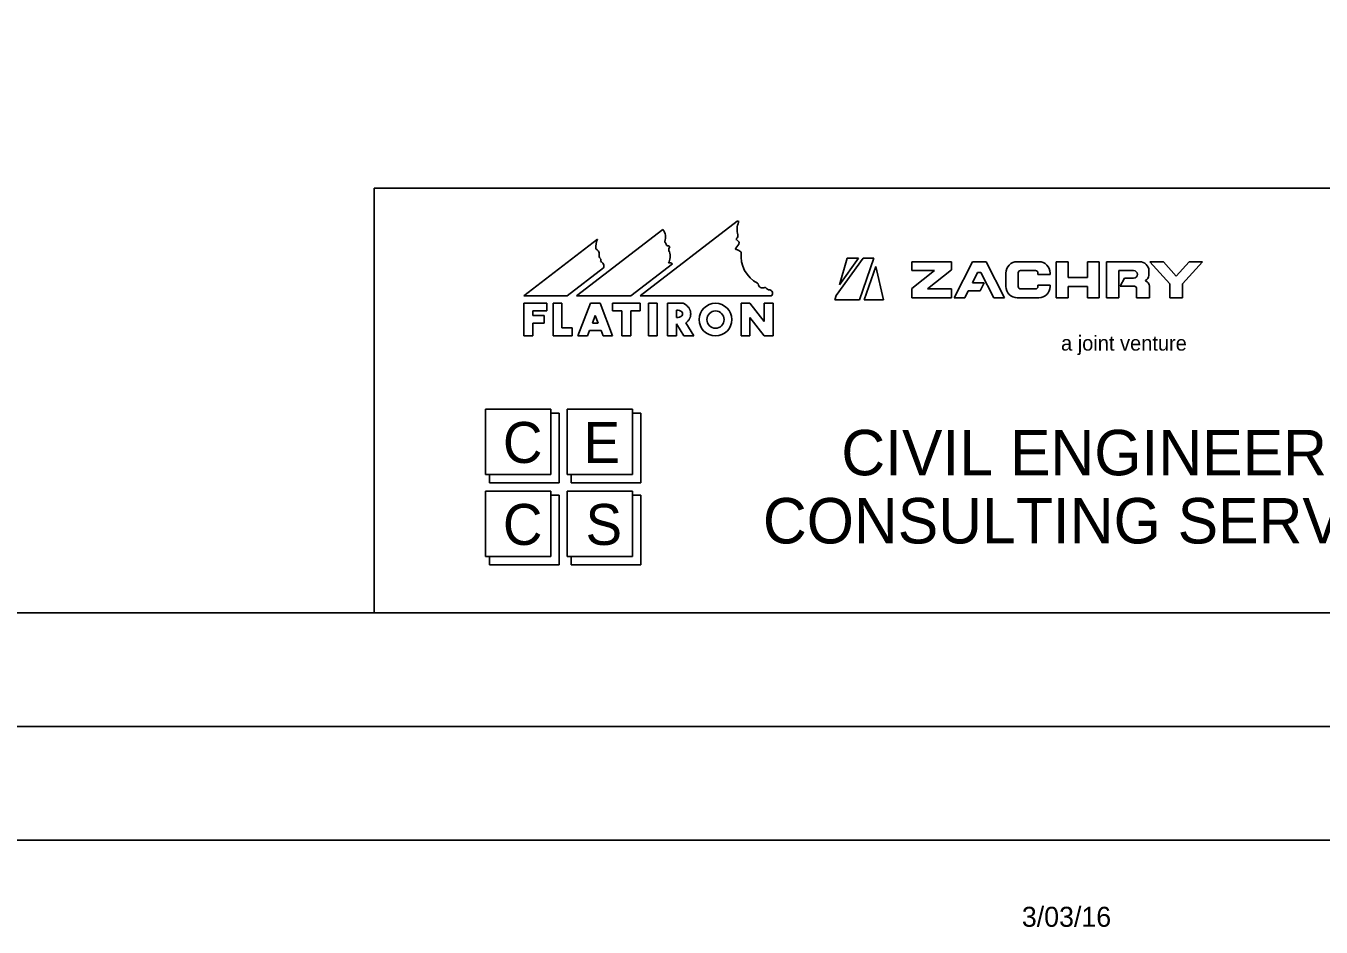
# Model space of a CAD drawing. Extents: x -2251 to 10196, y -13470 to 1199.
# Drawn here: x 6237 to 6522.4, y -1469.8 to -1271.4 of the extents above; entities that cross this region are included whole.
import ezdxf

# ---------------------------------------------------------------- set-up
doc = ezdxf.new("R2010")
doc.units = 0
for name, color, linetype in [('Level 3', 7, 'Continuous'), ('RD_SHT_Bndy', 7, 'Continuous'), ('RD_SHT_Iplotshp', 7, 'Continuous'), ('RD_SHT_Logo', 7, 'Continuous'), ('RD_SHT_Misc1', 7, 'Continuous'), ('RD_SHT_Snap', 7, 'Continuous'), ('RD_SHT_TX', 7, 'Continuous')]:
    doc.layers.add(name, color=color, linetype=linetype)

msp = doc.modelspace()

# ---------------------------------------------------------------- linework, layer by layer
at = {"layer": 'Level 3'}
msp.add_line((6465.07, -1363.99), (6465.07, -1363.99), dxfattribs=at)
msp.add_line((6465.07, -1363.99), (6465.07, -1363.99), dxfattribs=at)
msp.add_line((6465.07, -1363.99), (6465.07, -1363.99), dxfattribs=at)
msp.add_line((6465.07, -1363.99), (6465.07, -1363.99), dxfattribs=at)
at = {"layer": 'RD_SHT_Bndy'}
for p, q in [((5103.1, -1400.65), (6778.1, -1400.65)), ((6791.65, -1425.65), (5031.65, -1425.65)), ((6791.6, -1450.7), (5031.6, -1450.65))]:
    msp.add_line(p, q, dxfattribs=at)
at = {"layer": 'RD_SHT_Iplotshp'}
msp.add_lwpolyline([(4996.65, -325.65), (6796.65, -325.65), (6796.65, -1425.65), (4996.65, -1425.65)], close=True, dxfattribs=at)
at = {"layer": 'RD_SHT_Logo'}
for p, q in [((6372.32, -1330.86), (6393.74, -1314.44)), ((6346.7, -1330.86), (6362.98, -1318.38)), ((6377.35, -1316.27), (6358.31, -1330.86)), ((6370.3, -1330.86), (6379.48, -1323.82)), ((6415.56, -1330.77), (6421.47, -1322.59)), ((6420.48, -1322.59), (6416.24, -1328.47)), ((6416.24, -1328.47), (6417.96, -1322.59)), ((6417.96, -1322.59), (6420.48, -1322.59)), ((6423.82, -1322.59), (6420.68, -1331.76)), ((6421.47, -1322.59), (6423.82, -1322.59)), ((6440.93, -1323.35), (6432.22, -1323.35)), ((6432.22, -1323.35), (6432.22, -1325.3)), ((6440.93, -1325.16), (6440.93, -1323.35)), ((6445.58, -1323.35), (6441.53, -1331.3)), ((6448.58, -1323.35), (6445.58, -1323.35)), ((6452.63, -1331.3), (6448.58, -1323.35)), ((6455.44, -1323.35), (6460.18, -1323.35)), ((6466.62, -1323.35), (6464.02, -1323.35)), ((6464.02, -1323.35), (6464.02, -1331.3)), ((6466.62, -1326.8), (6466.62, -1323.35)), ((6470.9, -1323.35), (6470.9, -1326.8)), ((6473.51, -1323.35), (6470.9, -1323.35)), ((6473.5, -1331.3), (6473.51, -1323.35)), ((6482.43, -1323.35), (6475.13, -1323.35)), ((6475.13, -1323.35), (6475.13, -1331.3)), ((6484.68, -1323.35), (6487.64, -1323.35)), ((6489.08, -1328.24), (6484.68, -1323.35)), ((6487.64, -1323.35), (6490.48, -1326.51)), ((6490.48, -1326.51), (6493.32, -1323.35)), ((6496.28, -1323.35), (6491.88, -1328.24)), ((6493.32, -1323.35), (6496.28, -1323.35)), ((6364.27, -1324.74), (6356.29, -1330.86)), ((6424.24, -1324.44), (6421.74, -1331.76)), ((6425.99, -1331.76), (6424.24, -1324.44)), ((6437.2, -1325.3), (6432.22, -1329.24)), ((6432.22, -1325.3), (6437.2, -1325.3)), ((6435.63, -1329.35), (6440.93, -1325.16)), ((6445.57, -1327.99), (6446.71, -1325.75)), ((6446.71, -1325.75), (6447.44, -1325.75)), ((6447.44, -1325.75), (6450.27, -1331.3)), ((6452.94, -1328.8), (6452.94, -1325.85)), ((6455.64, -1325.8), (6455.64, -1328.85)), ((6459.48, -1325.3), (6456.14, -1325.3)), ((6459.98, -1326.15), (6459.98, -1325.8)), ((6462.68, -1326.15), (6459.98, -1326.15)), ((6462.68, -1325.85), (6462.68, -1326.15)), ((6470.9, -1326.8), (6466.62, -1326.8)), ((6477.83, -1331.3), (6477.83, -1325.31)), ((6477.83, -1325.31), (6481.07, -1325.31)), ((6479.03, -1326.97), (6478.11, -1328.77)), ((6481.07, -1326.97), (6479.03, -1326.97)), ((6484.43, -1326.36), (6484.43, -1325.35)), ((6432.22, -1329.24), (6432.22, -1331.3)), ((6440.93, -1329.35), (6435.63, -1329.35)), ((6440.93, -1331.3), (6440.93, -1329.35)), ((6443.88, -1331.3), (6444.65, -1329.79)), ((6444.65, -1329.79), (6447.23, -1329.79)), ((6448.15, -1327.99), (6445.57, -1327.99)), ((6447.23, -1329.79), (6448.15, -1327.99)), ((6456.14, -1329.35), (6459.48, -1329.35)), ((6459.98, -1328.5), (6462.68, -1328.5)), ((6459.98, -1328.85), (6459.98, -1328.5)), ((6462.68, -1328.5), (6462.68, -1328.8)), ((6466.62, -1331.3), (6466.62, -1328.8)), ((6466.62, -1328.8), (6470.9, -1328.8)), ((6470.9, -1328.8), (6470.9, -1331.3)), ((6478.11, -1328.77), (6481.24, -1328.77)), ((6481.74, -1329.27), (6481.74, -1331.3)), ((6483.68, -1327.6), (6483.68, -1327.47)), ((6484.54, -1331.3), (6484.54, -1328.76)), ((6489.08, -1331.3), (6489.08, -1328.24)), ((6491.88, -1328.24), (6491.88, -1331.3)), ((6356.29, -1330.86), (6346.7, -1330.86)), ((6346.72, -1339.7), (6346.72, -1332.5)), ((6346.72, -1332.5), (6351.82, -1332.5)), ((6351.82, -1332.5), (6351.82, -1334.15)), ((6355.12, -1332.5), (6353.17, -1332.5)), ((6353.17, -1332.5), (6353.17, -1339.7)), ((6355.12, -1337.9), (6355.12, -1332.5)), ((6358.31, -1330.86), (6370.3, -1330.86)), ((6361.42, -1332.5), (6358.65, -1339.71)), ((6363.52, -1332.5), (6361.42, -1332.5)), ((6366.28, -1339.71), (6363.52, -1332.5)), ((6366.22, -1334.15), (6366.22, -1332.5)), ((6366.22, -1332.5), (6372.37, -1332.5)), ((6401.19, -1330.86), (6372.32, -1330.86)), ((6372.37, -1332.5), (6372.37, -1334.15)), ((6374.17, -1339.71), (6374.17, -1332.5)), ((6374.17, -1332.5), (6376.12, -1332.5)), ((6376.12, -1332.5), (6376.12, -1339.71)), ((6381.8, -1332.5), (6378.38, -1332.5)), ((6378.38, -1332.5), (6378.38, -1339.71)), ((6396.52, -1332.5), (6394.57, -1332.5)), ((6394.57, -1332.5), (6394.57, -1339.71)), ((6399.67, -1336.53), (6396.52, -1332.5)), ((6401.62, -1332.5), (6399.67, -1332.5)), ((6399.67, -1332.5), (6399.67, -1336.53)), ((6401.62, -1339.71), (6401.62, -1332.5)), ((6415.27, -1331.76), (6415.56, -1330.77)), ((6420.68, -1331.76), (6415.27, -1331.76)), ((6421.74, -1331.76), (6425.99, -1331.76)), ((6432.22, -1331.3), (6440.93, -1331.3)), ((6441.53, -1331.3), (6443.88, -1331.3)), ((6450.27, -1331.3), (6452.63, -1331.3)), ((6460.18, -1331.3), (6455.44, -1331.3)), ((6464.02, -1331.3), (6466.62, -1331.3)), ((6470.9, -1331.3), (6473.5, -1331.3)), ((6475.13, -1331.3), (6477.83, -1331.3)), ((6481.74, -1331.3), (6484.54, -1331.3)), ((6491.88, -1331.3), (6489.08, -1331.3)), ((6351.82, -1334.15), (6348.67, -1334.15)), ((6348.67, -1334.15), (6348.67, -1335.21)), ((6348.67, -1335.21), (6351.22, -1335.21)), ((6351.22, -1335.21), (6351.22, -1336.86)), ((6361.83, -1336.86), (6362.47, -1335.2)), ((6362.47, -1335.2), (6363.1, -1336.86)), ((6368.32, -1334.15), (6366.22, -1334.15)), ((6368.32, -1339.71), (6368.32, -1334.15)), ((6372.37, -1334.15), (6370.27, -1334.15)), ((6370.27, -1334.15), (6370.27, -1339.71)), ((6380.33, -1335.66), (6380.33, -1334.01)), ((6351.22, -1336.86), (6348.67, -1336.86)), ((6348.67, -1336.86), (6348.67, -1339.7)), ((6357.37, -1337.9), (6355.12, -1337.9)), ((6357.37, -1339.71), (6357.37, -1337.9)), ((6363.1, -1336.86), (6361.83, -1336.86)), ((6380.33, -1339.71), (6380.33, -1337.02)), ((6380.33, -1337.02), (6381.94, -1339.71)), ((6384.16, -1339.71), (6382.43, -1336.82)), ((6396.52, -1339.71), (6396.52, -1335.67)), ((6396.52, -1335.67), (6399.67, -1339.71)), ((6348.67, -1339.7), (6346.72, -1339.7)), ((6353.17, -1339.7), (6357.37, -1339.71)), ((6358.65, -1339.71), (6360.74, -1339.71)), ((6360.74, -1339.71), (6361.2, -1338.51)), ((6361.2, -1338.51), (6363.74, -1338.51)), ((6363.74, -1338.51), (6364.2, -1339.71)), ((6364.2, -1339.71), (6366.28, -1339.71)), ((6370.27, -1339.71), (6368.32, -1339.71)), ((6376.12, -1339.71), (6374.17, -1339.71)), ((6378.38, -1339.71), (6380.33, -1339.71)), ((6381.94, -1339.71), (6384.16, -1339.71)), ((6394.57, -1339.71), (6396.52, -1339.71)), ((6399.67, -1339.71), (6401.62, -1339.71)), ((6352.67, -1355.79), (6338.28, -1355.79)), ((6338.28, -1355.79), (6338.28, -1370.23)), ((6352.67, -1370.23), (6352.67, -1355.79)), ((6352.67, -1355.79), (6352.67, -1370.23)), ((6354.48, -1356.7), (6352.67, -1356.7)), ((6354.48, -1372.03), (6354.48, -1356.7)), ((6370.67, -1355.79), (6356.27, -1355.79)), ((6356.27, -1355.79), (6356.27, -1370.23)), ((6370.67, -1370.23), (6370.67, -1355.79)), ((6370.67, -1355.79), (6370.67, -1370.23)), ((6372.48, -1356.7), (6370.67, -1356.7)), ((6372.48, -1372.03), (6372.48, -1356.7)), ((6338.28, -1370.23), (6352.67, -1370.23)), ((6352.67, -1370.23), (6339.17, -1370.23)), ((6339.17, -1370.23), (6339.17, -1372.03)), ((6339.17, -1372.03), (6354.48, -1372.03)), ((6356.27, -1370.23), (6370.67, -1370.23)), ((6370.67, -1370.23), (6357.18, -1370.23)), ((6357.18, -1370.23), (6357.18, -1372.03)), ((6357.18, -1372.03), (6372.48, -1372.03)), ((6352.67, -1373.84), (6338.28, -1373.84)), ((6338.28, -1373.84), (6338.28, -1388.27)), ((6352.67, -1388.27), (6352.67, -1373.84)), ((6352.67, -1373.84), (6352.67, -1388.27)), ((6354.48, -1374.74), (6352.67, -1374.74)), ((6354.48, -1390.07), (6354.48, -1374.74)), ((6370.67, -1373.84), (6356.27, -1373.84)), ((6356.27, -1373.84), (6356.27, -1388.27)), ((6370.67, -1388.27), (6370.67, -1373.84)), ((6370.67, -1373.84), (6370.67, -1388.27)), ((6372.48, -1374.74), (6370.67, -1374.74)), ((6372.48, -1390.07), (6372.48, -1374.74)), ((6338.28, -1388.27), (6352.67, -1388.27)), ((6352.67, -1388.27), (6339.17, -1388.27)), ((6339.17, -1388.27), (6339.17, -1390.07)), ((6356.27, -1388.27), (6370.67, -1388.27)), ((6370.67, -1388.27), (6357.18, -1388.27)), ((6357.18, -1388.27), (6357.18, -1390.07)), ((6339.17, -1390.07), (6354.48, -1390.07)), ((6357.18, -1390.07), (6372.48, -1390.07))]:
    msp.add_line(p, q, dxfattribs=at)
for radius in [3.6, 1.9]:
    msp.add_circle((6388.95, -1336.1), radius, dxfattribs=at)
for centre, radius, start, end in [((6397.87, -1316.34), 4.17, 156.4699, 195.3053), ((6393.86, -1314.6), 0.2, 336.4699, 127.4657), ((6366.29, -1320.12), 3.74, 152.2252, 185.8662), ((6375.05, -1318.02), 2.89, 342.0343, 37.2653), ((6393.73, -1318.39), 0.2, 129.4079, 246.863), ((6393.13, -1317.66), 0.749, 309.4079, 17.0499), ((6362.1, -1321.62), 1.21, 351.6466, 67.1294), ((6377.99, -1318.97), 0.2, 162.0343, 220.8638), ((6376.86, -1319.95), 1.3, 11.8745, 40.8638), ((6378.32, -1319.64), 0.2, 191.8745, 279.8173), ((6378.44, -1320.33), 0.499, 44.4799, 99.8173), ((6375.8, -1322.18), 3.16, 331.2486, 18.4584), ((6379.5, -1320.72), 0.843, 144.641, 212.5499), ((6378.65, -1320.12), 0.2, 324.641, 44.4799), ((6393.57, -1320.5), 0.2, 133.0036, 262.3069), ((6391.59, -1318.37), 2.7, 313.0036, 343.6807), ((6393.31, -1322.44), 1.76, 45.283, 82.3069), ((6393.27, -1319.47), 0.973, 20.4113, 66.863), ((6394.4, -1321.33), 0.2, 353.8329, 45.283), ((6364.29, -1321.94), 1, 171.6466, 221.9371), ((6363.11, -1323.01), 0.592, 327.6019, 41.9371), ((6363.3, -1324.33), 1.05, 337.4201, 73.1261), ((6378.92, -1324.44), 0.827, 48.0701, 115.7229), ((6401.36, -1322.08), 6.8, 173.8329, 242.3928), ((6455.44, -1325.85), 2.5, 89.9984, 179.9984), ((6460.18, -1325.85), 2.5, 359.9984, 89.9984), ((6482.43, -1325.35), 2, 359.9984, 89.9984), ((6456.14, -1325.8), 0.5, 89.9984, 179.9984), ((6459.48, -1325.8), 0.5, 359.9984, 89.9984), ((6481.07, -1326.14), 0.831, 269.9984, 89.9984), ((6483.23, -1326.36), 1.2, 291.95, 359.9984), ((6398.12, -1328.28), 0.2, 9.0833, 62.3928), ((6399.35, -1328.09), 1.04, 189.0833, 295.769), ((6399.89, -1329.21), 0.2, 33.7112, 115.769), ((6400.89, -1328.54), 1.01, 213.7112, 268.6299), ((6400.86, -1329.74), 0.2, 78.9712, 88.6299), ((6400.75, -1330.3), 0.767, 320.912, 78.9712), ((6455.44, -1328.8), 2.5, 179.9984, 269.9984), ((6456.14, -1328.85), 0.5, 179.9984, 269.9984), ((6459.48, -1328.85), 0.5, 269.9984, 359.9984), ((6460.18, -1328.8), 2.5, 269.9984, 359.9984), ((6481.24, -1329.27), 0.5, 359.9984, 89.9984), ((6483.34, -1328.76), 1.2, 359.9984, 73.7977), ((6401.19, -1330.66), 0.2, 269.9984, 320.912)]:
    msp.add_arc(centre, radius, start, end, dxfattribs=at)
msp.add_ellipse((6380.33, -1334.83), major_axis=(1.36, 0), ratio=0.609965, start_param=4.712389, end_param=7.853982, dxfattribs=at)
msp.add_open_spline([(6382.43, -1336.82), (6382.51, -1336.76), (6382.59, -1336.7), (6382.81, -1336.49), (6382.95, -1336.34), (6383.13, -1336.07), (6383.19, -1335.97), (6383.29, -1335.77), (6383.34, -1335.66), (6383.41, -1335.44), (6383.44, -1335.32), (6383.47, -1335.08), (6383.48, -1334.96), (6383.48, -1334.71), (6383.47, -1334.59), (6383.44, -1334.35), (6383.41, -1334.23), (6383.34, -1334.01), (6383.29, -1333.9), (6383.19, -1333.7), (6383.13, -1333.6), (6382.95, -1333.33), (6382.81, -1333.18), (6382.52, -1332.91), (6382.37, -1332.8), (6382.08, -1332.63), (6381.94, -1332.56), (6381.8, -1332.5)], degree=3, dxfattribs=at)
at = {"layer": 'RD_SHT_Misc1'}
msp.add_lwpolyline([(6796.65, -1425.65), (6796.68, -325.65), (5096.68, -325.6), (5096.65, -1425.6)], close=True, dxfattribs=at)
at = {"layer": 'RD_SHT_Snap'}
msp.add_lwpolyline([(5008.15, -325.65), (6808.15, -325.65), (6808.15, -1425.65), (5008.15, -1425.65)], close=True, dxfattribs=at)
at = {"layer": 'RD_SHT_TX'}
for p, q in [((6313.76, -1400.65), (6313.76, -1307.15)), ((6313.76, -1400.65), (6313.76, -1307.15)), ((6313.76, -1307.15), (6778.1, -1307.15))]:
    msp.add_line(p, q, dxfattribs=at)

# ---------------------------------------------------------------- texts
at = {"layer": 'RD_SHT_Logo'}
msp.add_text('a joint venture', height=3.3, rotation=359.9984, dxfattribs=at).set_placement((6465.08, -1342.93))
for s, height, p in [('C', 9.02, (6342.11, -1367.66)), ('E', 9.02, (6359.9, -1367.66)), ('CIVIL ENGINEERING', 10, (6416.67, -1370.38)), ('CONSULTING SERVICES, INC.', 10, (6399.39, -1385.38)), ('C', 9.02, (6342.11, -1385.71)), ('S', 9.02, (6360.32, -1385.71))]:
    msp.add_text(s, height=height, dxfattribs=at).set_placement(p)
at = {"layer": 'RD_SHT_TX'}
msp.add_text('3/03/16', height=4.408, dxfattribs=at).set_placement((6456.45, -1469.78))

doc.saveas('drawing.dxf')
